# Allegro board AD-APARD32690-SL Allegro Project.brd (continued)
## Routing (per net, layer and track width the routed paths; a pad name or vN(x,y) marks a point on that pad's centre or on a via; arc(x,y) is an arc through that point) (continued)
UNNAMED_3_ADMAX32690_I367_P1_11: length 86.9
  TOP w0.127: U1.A5 v2(98.93,28.05)
  L2_GND w0.102: v2(98.93,28.05) v3(98.32,28.05)
  L3_SIG w0.089: v1(87.12,9.65) 87.12,9.14 88.8,7.46 92.36,7.46 93.66,6.16 132.59,6.16 v1(133.6,7.18) ; v1(86.58,21.88) 89.03,24.32 95.5,24.32 96.96,25.78 96.96,26.7 v3(98.32,28.05)
  L8_SIG w0.089: v1(86.58,21.88) 87.12,21.34 v1(87.12,9.65)
  BOTTOM w0.127: v1(133.6,7.18) 141.99,7.18 142.25,7.44 142.25,8.38 R35.2
UNNAMED_3_ADMAX32690_I367_P1_12: length 53.3
  TOP w0.127: R36.2 v1(128.21,32.77)
  L3_SIG w0.089: v3(100.6,27.7) 99.95,27.05 99.95,25.59 v4(99.63,25.27)
  L4_GND w0.102: v1(97.66,20.13) 97.98,20.45 97.98,23.62 v4(99.63,25.27)
  BOTTOM w0.127: v1(128.21,32.77) 127.44,32 127.44,29.97 122.49,25.02 122.49,19.37 120.21,17.08 98.93,17.08 97.66,18.35 v1(97.66,20.13)
UNNAMED_3_ADMAX32690_I367_P1_15: length 9.3
  L2_GND w0.102: v1(94.09,27.94) 94.55,28.4 v2(99.9,28.4)
  BOTTOM w0.127: v1(94.09,27.94) R38.2
UNNAMED_3_ADMAX32690_I367_P1_16: length 57.3
  TOP w0.102: U1.B1 99.57,26.32
  TOP w0.127: v1(93.3,19.32) 94.03,19.32 96.76,22.05 96.76,23.51 99.57,26.32 ; R37.2 v1(128.21,29.84)
  BOTTOM w0.127: v1(128.21,29.84) 128.21,29.46 127.76,29.02 127.76,26.73 123.25,22.23 123.25,19.11 120.46,16.32 94.55,16.32 93.66,17.21 93.66,18.95 v1(93.3,19.32)
UNNAMED_3_ADMAX32690_I367_P1_19: length 83
  TOP w0.127: R69.2 52.09,47.43 v1(52.83,47.43)
  L3_SIG w0.089: v3(102.7,29.1) 102.84,28.96 103.02,28.96 104.55,27.43 106.84,27.43 106.97,27.3 110.81,27.3 v1(111.2,27.7) ; v1(105.79,43.5) 101.98,43.5 101.47,44.01 63.94,44.01 61.47,46.48 53.78,46.48 v1(52.83,47.43)
  BOTTOM w0.127: v1(105.79,43.5) 105.79,41.08 111.46,35.42 111.46,27.96 v1(111.2,27.7)
UNNAMED_3_ADMAX32690_I367_P1_20: length 20.9
  TOP w0.127: v1(116.2,19.75) 116.8,19.75 R71.2
  L3_SIG w0.089: v3(102.7,28.75) 102.85,28.6 103.02,28.6 104.7,26.92 106.55,26.92 106.71,26.77 113.16,26.77 114.3,25.62 v1(115.32,25.62)
  BOTTOM w0.127: v1(116.2,19.75) 115.32,20.64 v1(115.32,25.62)
UNNAMED_3_ADMAX32690_I367_P1_21: length 66.8
  TOP w0.127: R70.2 61.29,47.38 v1(62.36,47.38)
  L3_SIG w0.089: v1(62.36,47.38) 63.87,47.38 66.48,44.77 103.44,44.77 v1(103.82,44.39)
  L5_PWR w0.102: v1(103.82,44.39) 104.97,43.24 104.97,41.72 105.47,41.21 105.47,32.32 106.74,31.05 106.74,28.07 106.36,27.69 103.92,27.69 103.47,28.13 102.62,28.13 v5(102,28.75)
UNNAMED_3_ADMAX32690_I367_P1_22: length 85.8
  TOP w0.127: U1.M7 103.58,28.75 104.04,29.21 105.12,29.21 105.44,28.89 105.82,28.89 106.08,28.64 108.55,28.64 108.74,28.83 v1(112.52,28.83) ; R72.2 49.55,47.43 v1(50.29,47.43)
  L3_SIG w0.089: v1(50.29,47.43) 51.5,46.23 61.34,46.23 63.94,43.62 101.41,43.62 101.92,43.12 v1(106.81,43.12)
  BOTTOM w0.127: v1(106.81,43.12) 107.19,42.74 107.19,41.28 112.6,35.86 112.6,33.26 113.09,32.77 113.09,29.94 112.52,29.37 v1(112.52,28.83)
UNNAMED_3_ADMAX32690_I367_P1_23: length 55.4
  TOP w0.127: v1(57.91,47.43) 57.17,47.43 R73.2
  L5_PWR w0.102: v1(57.91,47.43) 59.31,47.43 63.82,42.93 83.18,42.93 89.53,36.58 100.01,36.58 101.3,35.29 v5(101.3,29.1)
UNNAMED_3_ADMAX32690_I367_P1_24: length 91.1
  TOP w0.127: v1(45.21,47.43) 44.47,47.43 R44.2
  L2_GND w0.102: v2(103.05,29.1) 104.46,27.69 v3(104.71,27.69)
  L3_SIG w0.089: v1(45.21,47.43) 46.93,45.72 61.09,45.72 63.88,42.93 101.03,42.93 101.6,42.35 v1(106.24,42.35) ; v1(111.82,27.69) 111.44,28.07 111,28.07 110.49,27.56 107.09,27.56 106.97,27.69 v3(104.71,27.69)
  BOTTOM w0.127: v1(111.82,27.69) 111.82,29.75 112.33,30.26 112.33,32.54 111.84,33.04 111.84,35.54 106.24,41.15 v1(106.24,42.35)
UNNAMED_3_ADMAX32690_I367_P1_25: length 75.1
  TOP w0.127: v1(64.51,47.38) 63.83,47.38 R43.2
  L3_SIG w0.089: v1(105.35,44.39) 104.58,45.15 66.74,45.15 v1(64.51,47.38)
  L4_GND w0.102: v1(111.82,25.62) 110.84,26.61 106.68,26.61 106.11,27.18 104.2,27.18 102.63,28.75 v4(102.35,28.75)
  BOTTOM w0.127: v1(105.35,44.39) 105.35,41.02 110.17,36.2 110.17,27.56 111.82,25.91 v1(111.82,25.62)
UNNAMED_3_ADMAX32690_I367_P1_28: length 89.9
  TOP w0.127: v1(47.75,47.43) 47.01,47.43 R45.2
  L2_GND w0.102: v3(104.81,27.18) 104.62,27.18 v2(103.05,28.75)
  L3_SIG w0.089: v3(104.81,27.18) 106.71,27.18 106.84,27.05 111.89,27.05 v1(112.52,27.69) ; v1(106.81,42.35) 106.43,42.74 101.79,42.74 101.28,43.24 63.94,43.24 61.21,45.97 49.21,45.97 v1(47.75,47.43)
  BOTTOM w0.127: v1(106.81,42.35) 106.81,41.08 112.22,35.67 112.22,33.13 112.71,32.64 112.71,30.1 112.14,29.53 112.14,28.07 v1(112.52,27.69)
UNNAMED_3_ADMAX32690_I367_P1_29: length 63.6
  TOP w0.127: R46.2 54.63,47.43 v1(55.37,47.43)
  L3_SIG w0.089: v1(55.37,47.43) 56.07,46.74 61.59,46.74 63.94,44.39 v1(101.65,44.39)
  L5_PWR w0.102: v5(101.65,29.1) v1(101.65,44.39)
UNNAMED_3_ADMAX32690_I367_P1_30: length 8.3
  TOP w0.127: U1.A7 93.52,28.75 v1(92.58,27.81)
  BOTTOM w0.127: R47.2 v1(92.58,27.81)
UNNAMED_3_ADMAX32690_I367_P2: length 37.7
  TOP w0.127: v1(97.6,38.8) 92.14,44.26 77.53,44.26 76.45,45.34 R101.1
  L4_GND w0.102: v4(100.6,28.4) 99.38,29.62 99.38,31.08 98.23,32.23 98.23,37.34 97.6,37.97 v1(97.6,38.8)
UNNAMED_3_ADMAX32690_I367_P2_1: length 45.5
  TOP w0.127: v1(72.12,47.38) 71.49,47.38 R81.1 ; v1(98.42,39.56) 98.11,39.88 98.11,45.28 v1(97.85,45.53)
  L3_SIG w0.089: v1(97.85,45.53) 73.98,45.53 72.13,47.38 v1(72.12,47.38)
  L4_GND w0.102: v4(100.6,28.75) 99.73,29.62 99.73,31.18 98.55,32.35 98.55,37.72 98.04,38.23 98.04,39.18 v1(98.42,39.56)
UNNAMED_3_ADMAX32690_I367_P2_2: length 77.7
  L3_SIG w0.089: v1(95.5,9.43) 95.92,9.02 125.86,9.02 129.86,13.02 v1(133.6,13.02) ; v3(100.6,29.45) 98.81,31.24 v1(95.12,31.24)
  L8_SIG w0.089: v1(95.44,26.48) 96.14,25.78 96.14,10.06 v1(95.5,9.43)
  BOTTOM w0.127: R104.1 141.22,13.46 140.78,13.02 v1(133.6,13.02) ; v1(95.12,31.24) 95.12,29.59 94.96,29.43 94.96,26.96 v1(95.44,26.48)
UNNAMED_3_ADMAX32690_I367_P2_3: length 95.2
  TOP w0.127: R82.1 41.91,47.5 v1(42.74,46.67)
  L2_GND w0.102: v2(100.95,27) 100.95,26.65 v3(99.19,24.89)
  L3_SIG w0.089: v1(42.74,46.67) 43.94,45.47 60.9,45.47 65.34,41.02 66.42,41.02 67.88,39.56 67.88,18.1 71.18,14.8 78.93,14.8 79.98,15.84 83.69,15.84 84.11,15.43 86.55,15.43 87.88,16.76 87.88,17.81 91.98,21.91 96.2,21.91 v3(99.19,24.89)
UNNAMED_3_ADMAX32690_I367_P2_4: length 101.2
  TOP w0.127: v1(42.04,46.67) 37.97,46.67 37.4,46.1 35.81,46.1 35.56,46.36 R103.1
  L3_SIG w0.089: v3(100.95,27.35) 100.95,27.16 100.46,26.67 100.46,25.78 100.58,25.65 100.58,24.89 96.77,21.08 92.46,21.08 88.71,17.34 88.71,16.19 86.8,14.29 79.98,14.29 79.41,13.72 70.48,13.72 66.67,17.53 66.67,39.81 66.1,40.39 61.53,40.39 56.71,45.21 43.5,45.21 v1(42.04,46.67)
UNNAMED_3_ADMAX32690_I367_P2_5: length 52.8
  TOP w0.127: v1(74.68,47.38) 74.03,47.38 R80.1
  L3_SIG w0.089: v1(95.31,45.91) 76.14,45.91 74.68,47.37 v1(74.68,47.38)
  L5_PWR w0.102: v1(94.81,25.08) 95.22,25.5 99.76,25.5 100.71,26.45 100.71,28.16 v5(100.95,28.4)
  BOTTOM w0.127: v1(95.31,45.91) 95.82,45.4 95.82,32.89 96.46,32.26 96.46,26.35 95.19,25.08 v1(94.81,25.08)
UNNAMED_3_ADMAX32690_I367_P2_6: length 47.1
  TOP w0.127: R102.1 79.11,47.38 v1(79.75,47.38)
  L3_SIG w0.089: v1(79.75,47.38) 80.45,46.67 v1(94.93,46.67)
  L5_PWR w0.102: v1(94.81,25.65) 94.96,25.81 99.66,25.81 100.43,26.57 100.43,28.4 100.77,28.75 v5(100.95,28.75)
  BOTTOM w0.127: v1(94.93,46.67) 94.93,45.72 95.5,45.15 95.5,32.7 96.14,32.07 96.14,26.51 95.28,25.65 v1(94.81,25.65)
UNNAMED_3_ADMAX32690_I367_P2_7: length 90.9
  TOP w0.127: R83.1 48.63,6.53 50.41,6.53 52.07,8.19 53.28,8.19 54.17,9.08 54.17,23.18 54.8,23.81 67.12,23.81 68.77,25.46 v1(73.03,25.46)
  L3_SIG w0.089: v1(73.03,25.46) 73.03,38.74 73.98,39.69 95.63,39.69 97.73,37.59 v1(100.39,37.59)
  L4_GND w0.102: v1(100.39,37.59) 100.77,37.21 100.77,29.62 v4(100.95,29.45)
UNNAMED_3_ADMAX32690_I367_P2_8: length 19.9
  TOP w0.127: R105.1 98.87,46.16 98.87,40.45 99.69,39.62 v1(99.69,38.35)
  L4_GND w0.102: v1(99.69,38.35) 100.2,38.35 101.12,37.43 101.12,29.62 v4(101.3,29.45)
UNNAMED_3_ADMAX32690_I367_P2_9: length 25.2
  TOP w0.127: v1(102.17,36.2) 102.17,42.42 102.62,42.86 R106.1
  L3_SIG w0.089: v3(101.65,27.35) v1(101.65,25.08)
  L8_SIG w0.089: v1(102.17,36.2) 101.47,35.5 101.47,25.26 v1(101.65,25.08)
UNNAMED_3_ADMAX32690_I367_P2_10: length 22.6
  TOP w0.127: R84.1 95.11,47.38 95.94,47.38 96.55,46.77 97.57,46.77 98.49,45.85 98.49,40.26 99.25,39.5 v1(99.25,38.8)
  L4_GND w0.102: v4(101.65,29.45) 101.47,29.63 101.47,37.72 100.39,38.8 v1(99.25,38.8)
UNNAMED_3_ADMAX32690_I367_P2_11: length 54.2
  TOP w0.127: R77.1 84.95,47.38 v1(85.59,47.38)
  L3_SIG w0.089: v1(103.82,45.91) 103.06,46.67 98.93,46.67 97.09,48.51 92.65,48.51 92.27,48.13 90.3,48.13 89.98,47.82 87.95,47.82 87.51,47.38 v1(85.59,47.38)
  L4_GND w0.102: v1(109.82,25.02) 109.03,25.81 106.24,25.81 105.63,26.42 103.82,26.42 102.68,27.56 102.49,27.56 v4(102,28.05)
  L8_SIG w0.089: v1(109.82,25.02) 109.66,25.18 109.66,41.97 106.52,45.12 104.62,45.12 v1(103.82,45.91)
UNNAMED_3_ADMAX32690_I367_P2_12: length 37.7
  TOP w0.127: R74.1 126.06,11.3 126.06,12.25 124.9,13.4 116.59,13.4 115.32,14.67 115.32,21.02 114.24,22.1 106.49,22.1 v1(106.17,21.78)
  L5_PWR w0.102: v5(102,28.4) 102.52,27.88 103.31,27.88 104.58,26.61 104.58,25.21 105.73,24.07 105.73,22.99 106.17,22.54 v1(106.17,21.78)
UNNAMED_3_ADMAX32690_I367_P2_13: length 45.7
  TOP w0.127: R98.1 87.49,47.38 v1(88.13,47.38)
  L3_SIG w0.089: v1(102.08,21.91) 102.08,24.16 102.62,24.7 102.62,27.43 v3(102.35,27.7) ; v1(100.96,46.29) 98.81,46.29 96.96,48.13 92.77,48.13 92.46,47.82 90.49,47.82 90.05,47.38 v1(88.13,47.38)
  L8_SIG w0.089: v1(100.96,46.29) 100.96,24.96 102.08,23.84 v1(102.08,21.91)
UNNAMED_3_ADMAX32690_I367_P2_14: length 23.5
  TOP w0.127: R79.1 v1(116.08,28.83)
  L3_SIG w0.089: v3(102.7,28.05) 102.86,27.89 103.05,27.89 104.14,26.8 104.14,25.15 106.01,23.27 115.89,23.27 117.09,24.48 117.09,27.81 v1(116.08,28.83)
UNNAMED_3_ADMAX32690_I367_P2_15: length 19.6
  TOP w0.127: R76.1 106.74,20.1 107.85,21.2 v1(110.93,21.2)
  L4_GND w0.102: v1(110.93,25.02) 110.93,26.03 110.62,26.35 106.49,26.35 105.92,26.92 104.08,26.92 102.6,28.4 v4(102.35,28.4)
  L8_SIG w0.089: v1(110.93,21.2) v1(110.93,25.02)
UNNAMED_3_ADMAX32690_I367_P2_16: length 25.3
  TOP w0.127: R109.1 105.16,6.09 105.09,6.15 105.09,9.4 v1(106.55,10.86)
  L2_GND w0.102: v3(102.87,23.62) 102.87,26.67 102.7,26.84 v2(102.7,27)
  L3_SIG w0.089: v3(102.87,23.62) 102.87,11.49 103.76,10.6 106.3,10.6 v1(106.55,10.86)
UNNAMED_3_ADMAX32690_I367_P2_17: length 30.8
  TOP w0.127: v1(103.93,11.03) 100.65,7.75 93.54,7.75 92.46,6.67 R108.1
  L2_GND w0.102: v2(102.7,27.35) 103.19,26.86 v3(103.19,26.16)
  L3_SIG w0.089: v3(103.19,26.16) 103.19,11.78 v1(103.93,11.03)
UNNAMED_3_ADMAX32690_I367_P2_18: length 26.1
  TOP w0.127: R97.1 v1(107.7,11.24)
  L3_SIG w0.089: v1(107.7,11.24) 106.36,11.24 105.98,10.86 104.65,10.86 103.5,12 103.5,26.29 102.86,26.93 102.86,27.53 v3(102.7,27.7)
UNNAMED_3_ADMAX32690_I367_P2_19: length 16.9
  TOP w0.127: v1(110.36,25.62) 110.36,26.42 110.87,26.92 116.33,26.92 R100.1
  L4_GND w0.102: v4(102.35,28.05) 102.57,28.05 103.95,26.67 105.73,26.67 106.33,26.07 109.92,26.07 v1(110.36,25.62)
UNNAMED_3_ADMAX32690_I367_P2_20: length 18.4
  TOP w0.127: R96.1 109.54,20.1 110.14,20.7 111.35,20.7 v1(111.82,21.18)
  L3_SIG w0.089: v1(111.82,24) 111.35,23.53 106.2,23.53 104.44,25.29 104.44,26.85 103.05,28.24 102.85,28.24 v3(102.7,28.4)
  L8_SIG w0.089: v1(111.82,21.18) v1(111.82,24)
UNNAMED_3_ADMAX32690_I367_P2_21: length 27
  TOP w0.127: U1.L1 103.05,26.21 104.01,25.24 104.01,21.59 v1(105.09,20.51) ; v1(105.28,12.07) 105.28,11.3 100.96,6.99 97.85,6.99 97.54,6.67 R87.1
  L3_SIG w0.089: v1(105.09,20.51) 104.65,20.07 104.65,13.72 105.28,13.08 v1(105.28,12.07)
UNNAMED_3_ADMAX32690_I367_P2_22: length 29.6
  TOP w0.102: 103.38,26.32 103.38,26.67 U1.L2
  TOP w0.127: v1(105.09,21.15) 104.33,21.91 104.33,25.37 103.38,26.32 ; v1(104.84,11.68) 104.84,11.37 100.84,7.37 95.57,7.37 95,6.79 R107.1
  L3_SIG w0.089: v1(105.09,21.15) 104.33,20.38 104.33,12.7 104.84,12.19 v1(104.84,11.68)
UNNAMED_3_ADMAX32690_I367_P2_23: length 24.4
  TOP w0.127: R88.1 102.62,8.13 v1(105.73,11.24)
  L2_GND w0.102: v3(103.63,26.54) 103.63,26.77 v2(103.05,27.35)
  L3_SIG w0.089: v1(105.73,11.24) 104.68,11.24 103.82,12.1 103.82,26.35 v3(103.63,26.54)
UNNAMED_3_ADMAX32690_I367_P2_24: length 39.7
  TOP w0.127: v1(100.97,47.38) 100.19,47.38 R85.1
  L2_GND w0.102: v3(105.6,25.59) 105.16,25.59 v2(103.05,27.7)
  L3_SIG w0.089: v3(105.6,25.59) 108.65,25.59 109.63,24.61 111.41,24.61 v1(111.82,25.02)
  BOTTOM w0.127: v1(100.97,47.38) 100.98,47.37 103.89,47.37 104.9,46.36 104.9,40.89 109.85,35.94 109.85,27.43 111.38,25.91 111.38,25.46 v1(111.82,25.02)
UNNAMED_3_ADMAX32690_I367_P2_25: length 45.7
  TOP w0.127: v1(93.21,47.38) 92.57,47.38 R99.1
  L2_GND w0.102: v3(104.9,26.35) 104.75,26.35 v2(103.05,28.05)
  L3_SIG w0.089: v1(105.35,45.53) 98.55,45.53 96.7,47.38 v1(93.21,47.38) ; v1(110.36,25.02) 109.35,26.04 106.62,26.04 106.23,26.42 105.1,26.42 105.03,26.35 v3(104.9,26.35)
  L8_SIG w0.089: v1(110.36,25.02) 110.33,25.02 110.01,25.34 110.01,42.23 106.71,45.53 v1(105.35,45.53)
UNNAMED_3_ADMAX32690_I367_P2_26: length 23.7
  TOP w0.127: v1(108.58,20.19) 108.27,20.19 108.14,20.07 R75.1
  L2_GND w0.102: v2(103.05,28.4) 104.78,26.67 v3(104.9,26.67)
  L3_SIG w0.089: v1(113.73,25.62) 112.97,26.38 106.68,26.38 106.39,26.67 v3(104.9,26.67)
  L8_SIG w0.089: v1(108.58,20.19) 109.16,19.62 112.78,19.62 113.73,20.57 v1(113.73,25.62)
UNNAMED_3_ADMAX32690_I367_P2_27: length 34
  TOP w0.127: v1(104.39,12.07) 100.46,8.13 90.8,8.13 89.92,7.24 R86.1 ; v1(105.09,21.78) 104.65,22.23 104.65,25.5 103.7,26.45 103.7,26.86 103.56,27 U1.M2
  L3_SIG w0.089: v1(105.09,21.78) 104.08,20.76 104.08,12.38 v1(104.39,12.07)
UNNAMED_3_ADMAX32690_I367_P2_28: length 33.2
  TOP w0.127: v1(104.24,28.42) 103.87,28.05 U1.M5 ; R78.1 90.03,47.38 v1(90.67,47.38)
  L3_SIG w0.089: v1(90.67,47.38) 92.53,47.38 92.96,47.82 96.77,47.82 98.68,45.91 v1(101.66,45.91)
  L8_SIG w0.089: v1(104.24,28.42) 104.46,28.64 104.46,44.32 102.87,45.91 v1(101.66,45.91)
UNNAMED_3_ADMAX32690_I367_P2_29: length 22.5
  TOP w0.127: U1.M6 103.65,28.4 104.2,28.96 104.97,28.96 105.35,28.57 105.66,28.57 105.89,28.35 108.78,28.35 108.9,28.48 113.38,28.48 v1(113.73,28.83) ; v1(110.93,20.19) R95.1
  L8_SIG w0.089: v1(113.73,28.83) 113.22,28.32 113.22,20.76 112.65,20.19 v1(110.93,20.19)
UNNAMED_3_ADMAX32690_I367_P3: length 64.9
  TOP w0.127: R114.1 v1(128.21,34.23)
  L4_GND w0.102: v4(100.6,29.1) 100.08,29.62 100.08,31.27 98.87,32.48 98.87,35.69 99.31,36.13 v1(99.89,36.13)
  BOTTOM w0.127: v1(128.21,34.23) 127.13,33.15 127.13,30.16 122.11,25.15 122.11,19.49 120.71,18.1 104.01,18.1 102.55,19.56 102.55,26.61 100.77,28.38 100.77,35.24 v1(99.89,36.13)
UNNAMED_3_ADMAX32690_I367_P3_1: length 32.7
  TOP w0.127: v1(98.04,15.94) 98.67,16.57 103.06,16.57 R93.1
  L4_GND w0.102: v1(99.89,35.56) 99.89,34.73 100.43,34.19 100.43,29.62 v4(100.95,29.1)
  L8_SIG w0.089: v1(98.04,15.94) 98.04,25.97 98.68,26.61 98.68,33.34 99.89,34.54 v1(99.89,35.56)
UNNAMED_3_ADMAX32690_I367_P3_2: length 78.1
  TOP w0.127: R89.1 69.34,17.4 67.94,18.8 67.94,21.46 69.85,23.37 v1(71.31,23.37)
  L3_SIG w0.089: v3(100.95,29.8) 100.95,30.81 101.41,31.27 101.41,40.26 100.43,41.24 73.25,41.24 71.31,39.31 v1(71.31,23.37)
UNNAMED_3_ADMAX32690_I367_P3_3: length 77.3
  TOP w0.127: R110.1 70.87,16.38 68.26,18.99 68.26,21.21 69.85,22.8 v1(71.75,22.8)
  L2_GND w0.102: v2(100.95,30.15) 100.95,30.53 101.09,30.67 v3(101.09,31.4)
  L3_SIG w0.089: v1(71.75,22.8) 71.75,39.18 73.47,40.89 100.33,40.89 101.09,40.13 v3(101.09,31.4)
UNNAMED_3_ADMAX32690_I367_P3_4: length 75.9
  TOP w0.127: R90.1 72.39,7.75 72.96,8.32 72.96,14.8 68.58,19.18 68.58,20.95 69.91,22.29 v1(72.52,22.29) ; U1.E12 100.95,30.97 100.96,30.99 100.96,39.05 v1(100.39,39.62)
  L3_SIG w0.089: v1(72.52,22.29) 72.52,38.8 73.72,40 100.01,40 v1(100.39,39.62)
UNNAMED_3_ADMAX32690_I367_P3_5: length 79.9
  TOP w0.127: v1(70.87,21.72) 69.91,21.72 68.9,20.7 68.9,19.37 73.34,14.92 73.34,8.32 73.91,7.75 R111.1
  L3_SIG w0.089: v1(70.87,21.72) 70.87,39.43 73.06,41.62 100.49,41.62 101.7,40.42 101.7,31.21 101.3,30.81 v3(101.3,29.8)
UNNAMED_3_ADMAX32690_I367_P3_6: length 77
  TOP w0.127: v1(70.87,18.99) 74.49,15.37 74.49,13.46 81.53,6.41 R92.1 ; U1.F12 101.3,39.29 v1(100.14,40.45)
  L3_SIG w0.089: v1(70.87,18.99) 72.14,20.26 72.14,38.99 73.6,40.45 v1(100.14,40.45)
UNNAMED_3_ADMAX32690_I367_P3_7: length 82.6
  TOP w0.127: R91.1 76.45,7.84 73.72,10.57 73.72,15.05 69.21,19.56 69.21,20.45 69.85,21.08 v1(70.83,21.08)
  L3_SIG w0.089: v3(101.65,29.8) 101.65,30.78 102.01,31.15 102.01,32.39 102.58,32.96 102.58,39.97 100.58,41.97 72.83,41.97 70.42,39.56 70.42,21.49 v1(70.83,21.08)
UNNAMED_3_ADMAX32690_I367_P3_8: length 83.4
  TOP w0.127: v1(69.98,20.51) 69.53,20.07 69.53,19.69 74.1,15.11 74.1,13.21 78.99,8.32 R112.1
  L3_SIG w0.089: v1(69.98,20.51) 69.98,39.69 72.6,42.31 100.69,42.31 102.87,40.13 102.87,32.83 102.3,32.26 102.3,31.02 102,30.72 v3(102,29.8)
UNNAMED_3_ADMAX32690_I367_P3_9: length 88
  TOP w0.127: v1(69.98,19.88) 70.61,19.88 74.87,15.62 74.87,13.72 81.79,6.79 83.76,6.79 84.07,6.48 R113.1
  L3_SIG w0.089: v3(102.35,29.8) 102.35,30.66 103.16,31.46 103.16,40.29 100.81,42.64 72.36,42.64 69.53,39.81 69.53,20.32 v1(69.98,19.88)
UNNAMED_3_ADMAX32690_I367_P4: length 16.3
  TOP w0.127: R94.1 v1(116.17,31.18)
  L3_SIG w0.089: v1(116.17,31.18) 110.78,31.18 v1(109.32,29.72)
  L4_GND w0.102: v1(109.32,29.72) 108.49,28.89 105.22,28.89 105.03,29.08 103.5,29.08 102.93,29.65 102.2,29.65 v4(102,29.45)
UNNAMED_3_ADMAX32690_I367_VREG1: length 5.9
  TOP w0.127: 102.35,32.69 U1.J12
  TOP w0.254: 102.68,33.02 102.35,32.69
  TOP w0.305: 102.68,34.67 102.68,33.02
  TOP w0.381: C18.1 103.42,35.41 102.68,34.67
UNNAMED_3_ANT4PV3_I701_FEED: length 3.8
  TOP w0.152: L5.2 115.32,47.43 C43.2 115.31,49.98 ANT1.4
UNNAMED_3_DIOLED4PV5_I542_C1: length 1.5
  TOP w0.127: R122.2 120.88,3.56 D5.2
UNNAMED_3_DIOLED4PV5_I542_C2: length 1.5
  TOP w0.127: D5.4 119.91,3.56 R118.2
UNNAMED_3_DIOLED_I538_N: length 2.3
  TOP w0.127: DS2.C 125.1,2 R116.2
UNNAMED_3_NC2P_I646_N2: length 1.3
  TOP w0.127: P18.2 63.83,42.76 R127.2
UNNAMED_3_RES_I645_N1: length 1.5
  TOP w0.127: Q4.3 R127.1
UNNAMED_3_RES_I698_N1: length 2.1
  TOP w0.127: Q1.3 126.11,4.2 R116.1
UNNAMED_3_RES_I699_N1: length 1.7
  TOP w0.127: R118.1 Q2.3
UNNAMED_3_RES_I700_N1: length 1.7
  TOP w0.127: R122.1 Q3.3
UNNAMED_7_ADIN1110V2_I781_AVDDH1: length 5.3
  TOP w0.508: v1(58.23,37.91) C64.2 C90.1 58.87,35.83 E6.2
  BOTTOM w0.254: U2.16 58.49,37.65 v1(58.23,37.91) 58.47,38.15 U2.17
UNNAMED_7_ADIN1110V2_I781_AVDDL: length 5
  BOTTOM w0.254: C65.2 59.94,41.66 60.29,41.31 U2.22
  BOTTOM w0.381: E5.2 57.56,42.36 C88.1 C65.2
UNNAMED_7_ADIN1110V2_I781_CEXT2: length 2.2
  BOTTOM w0.254: 58.23,39.15 U2.19
  BOTTOM w0.508: 58.23,39.15 58.13,39.05 C72.2
UNNAMED_7_ADIN1110V2_I781_CEXT3: length 2.1
  BOTTOM w0.254: 58.25,40.32 58.92,39.65 U2.20
  BOTTOM w0.508: C73.1 57.73,40.32 58.25,40.32
UNNAMED_7_ADIN1110V2_I781_DLDO1P1: length 5.7
  BOTTOM w0.254: U2.24 61.29,42.1 C93.2 60.79,42.13 U2.23
  BOTTOM w0.508: C93.2 62.34,42.36 C68.1
UNNAMED_7_ADIN1110V2_I781_LED0: length 3.9
  TOP w0.127: v1(63.29,33.66) 64.26,33.66 64.83,33.08 R139.2
  BOTTOM w0.127: U2.3 v1(63.29,33.66)
UNNAMED_7_ADIN1110V2_I781_LED1: length 5.5
  TOP w0.127: R130.2 63.5,32.58 63.18,32.89 62.23,32.89 61.79,33.33 v1(61.79,33.66) 61.79,34.15 61.53,34.41 R128.2
  BOTTOM w0.127: v1(61.79,33.66) U2.6
UNNAMED_7_ADIN1110V2_I781_TEST1: length 3.1
  BOTTOM w0.127: R125.1 63.7,41.79 63.5,41.59 62.67,41.59 62.29,41.21 U2.26
UNNAMED_7_ADIN1110V2_I781_TX2P4ENN: length 1.5
  TOP w0.127: R137.2 65.31,39.65 v1(65.81,39.65)
  BOTTOM w0.127: U2.31 v1(65.81,39.65)
UNNAMED_7_CAP_I819_N1: length 10.1
  TOP w0.102: v1(42.88,32.82) 42.88,33.1 43.03,33.25 43.03,33.89 42.7,34.22 41.84,34.22 41.64,34.02 T1.7 40.21,34.02 40.01,34.22 39.62,34.22 38.87,33.46 C102.1 R150.1
  BOTTOM w0.102: v1(42.88,32.82) 42.88,33.26 42.33,33.81 R151.2
UNNAMED_7_CAP_I819_N2: length 17.9
  TOP w0.102: R150.2 C102.2 35.04,33.15 34.94,33.25 34.94,34.12 34.84,34.23 33.97,34.23 33.85,34.1 33.85,33.37 P54.1 32.38,33.37 32.38,34.12 32.28,34.23 29.79,34.23 29.69,34.12 L6.3 28.07,33.08 27.41,32.42 R154.1
UNNAMED_7_CAP_I823_N1: length 10.6
  TOP w0.102: R149.1 38.87,37.85 C101.1 38.87,35.23 39.62,34.47 40,34.47 40.19,34.67 T1.6 41.63,34.67 41.82,34.47 42.81,34.47 43.28,34 43.28,33.24 43.43,33.08 v1(43.43,32.82)
  BOTTOM w0.102: R148.2 44,33.81 43.43,33.24 v1(43.43,32.82)
UNNAMED_7_CAP_I823_N2: length 18
  TOP w0.102: R153.1 27.41,36.16 27.94,35.62 L6.4 29.69,34.58 29.79,34.48 32.28,34.48 32.38,34.58 32.38,35.34 P53.1 33.85,35.34 33.85,34.61 33.97,34.48 34.84,34.48 34.94,34.58 34.94,35.46 35.04,35.56 C101.2 35.87,37.85 R149.2
UNNAMED_7_CAP_I855_N1: length 4.8
  BOTTOM w0.254: R152.2 41.06,30.8 38.77,30.8 38.49,31.08 C105.1
UNNAMED_7_CAP_I861_N1: length 17.5
  TOP w0.381: T1.5 41.12,36.67 41.31,36.86 41.31,38.77 41.75,39.21 47.13,39.21 C97.1 v1(47.15,40.07) ; C99.2 v1(47.15,32.7)
  BOTTOM w0.381: v1(47.15,40.07) 47.15,36.39 C94.1 47.15,36.38 v1(47.15,32.7)
UNNAMED_7_CHOKE4PV5_I912_N1: length 8.7
  TOP w0.102: R153.2 24.41,36.16 23.88,35.62 L6.1 22.19,34.7 21.97,34.48 20.77,34.48 20.66,34.58 20.66,34.95 20.56,35.05 R155.1
UNNAMED_7_CHOKE4PV5_I912_N2: length 8.6
  TOP w0.102: R156.1 20.56,33.66 20.66,33.76 20.66,34.12 20.77,34.23 21.97,34.23 22.19,34 L6.2 23.75,33.08 24.41,32.42 R154.2
UNNAMED_7_DIOLED_I752_N: length 1.6
  TOP w0.127: R139.1 DS3.C
UNNAMED_7_DIOLED_I761_N: length 1.6
  TOP w0.127: R130.1 DS4.C
UNNAMED_7_RES_I857_N1: length 4.5
  TOP w0.203: v6(44.48,31.05) 44.48,33.82 44.68,34.02 T1.3
  BOTTOM w0.203: R152.1 v6(44.48,31.05)
UNNAMED_7_RES_I906_N2: length 1.7
  TOP w0.127: S4.3A R166.2
UNNAMED_7_RES_I907_N2: length 1.7
  TOP w0.127: R167.2 S4.2A
UNNAMED_7_RES_I909_N2: length 1.7
  TOP w0.127: 114.68,10.1 R138.2
UNNAMED_9_ADMAXQ1065_I325_CEXT: length 1.4
  TOP w0.127: U8.1 108.07,16.44 108.14,16.51
  TOP w0.457: C91.1 109.47,16.51 108.14,16.51
UNNAMED_9_ADMAXQ1065_I325_PDWN: length 3
  TOP w0.127: 105.54,13.72 105.4,13.58 ; 105.4,13.58 105.56,13.42 ; 105.4,13.58 U8.7 ; 105.4,13.58 104.38,13.58 R165.1 104.28,13.59 P23.1
UNNAMED_9_CAP_I264_N1: length 7.8
  TOP w0.508: P13.6 145.26,38.64 C111.1 143.04,38.62 C109.2 140.15,38.62 140.14,38.61 JP3.2
  TOP w0.762: P13.6 P13.12
UNNAMED_9_CAP_I265_N1: length 8.5
  TOP w0.508: P8.6 144.07,2.03 144.03,2 C114.1 142.13,2 C113.2 141.53,1.98 140.72,2.79 JP4.2
  TOP w0.762: P8.12 P8.6
UNNAMED_9_CN12PV3_I138_P1: length 8
  TOP w0.127: JP9.2 P8.1
UNNAMED_9_CN12PV3_I138_P2: length 5.6
  TOP w0.127: JP7.2 P8.2
UNNAMED_9_CN12PV3_I138_P3: length 8
  TOP w0.127: JP8.2 P8.3
UNNAMED_9_CN12PV3_I138_P4: length 5.6
  TOP w0.127: JP10.2 P8.4
UNNAMED_9_CN12PV3_I138_P8: length 11.6
  TOP w0.127: JP5.2 145.03,17.27 146.56,15.75 146.56,13.46 P8.8
UNNAMED_9_CN12PV3_I138_P9: length 13.7
  TOP w0.127: P8.9 146.56,8.38 146.56,6.54 145.92,5.91 144.08,5.91 142.75,4.57 JP6.2
UNNAMED_9_CN16PAB4GND_I308_N3: length 6.8
  TOP w0.508: P10.B5 5.4,25.98 4.83,25.4 4.83,20.33 R158.2
UNNAMED_9_CN16PAB4GND_I314_N3: length 2.5
  TOP w0.508: R157.2 10.09,28.53 P10.A5
USB_DN: length 111.5
  TOP w0.102: U1.C12 100.25,31.13 99.79,31.59 99.41,31.59 98.99,32.01 98.99,32.05 98.98,32.06
  TOP w0.152: v1(48.45,26.16) 48.16,25.86 47.96,25.86 47.82,26 47.82,26.26 47.66,26.41 47.43,26.41 47.26,26.24 47.26,25.15 47.45,24.96 66.1,24.96 70.74,29.59 70.74,39.37 73.28,41.91 91.5,41.91 98.55,34.86 98.55,32.48 98.98,32.06
  BOTTOM w0.152: L7.1 13.38,26.84 13.63,27.09 14.58,27.09 15.39,26.28 47.9,26.28 48.03,26.16 v1(48.45,26.16)
USB_DN_CM: length 5.5
  TOP w0.152: P10.A7 7.12,26.83 P10.B7
  BOTTOM w0.152: L7.2 10.72,26.84 10.47,27.09 10.01,27.09 9.68,26.76 D6.C 9.4,26.76 9.06,27.1 8.42,27.1 8.15,26.83 P10.A7
USB_DP: length 111.6
  TOP w0.102: 98.76,31.84 98.77,31.83 98.81,31.83 99.3,31.34 99.68,31.34 99.99,31.03 99.99,30.6 U1.B12
  TOP w0.152: 98.76,31.84 98.25,32.36 98.25,34.74 91.38,41.61 73.41,41.61 71.04,39.24 71.04,29.46 66.23,24.65 47.33,24.65 46.96,25.02 46.96,26.37 47.3,26.71 v1(48.45,26.71)
  BOTTOM w0.152: L7.4 13.38,27.64 13.63,27.39 14.71,27.39 15.51,26.59 47.9,26.59 48.03,26.71 v1(48.45,26.71)
USB_DP_CM: length 5.5
  BOTTOM w0.152: L7.3 10.72,27.64 10.47,27.39 10.01,27.39 9.68,27.72 D7.C 9.37,27.72 9.05,27.4 8.42,27.4 8.15,27.68 P10.A6 7.12,27.68 P10.B6
VPWR_IN: length 5.6
  TOP w1.016: F3.1 4.84,9.89 P14.2
VPWR_USB: length 34.3
  TOP w0.254: U4.7 46.31,17.59 46.06,17.84 v6(46.04,17.84) 45.81,17.62 U4.8
  TOP w0.406: P10.B9 P10.A4
  TOP w0.508: P10.B4 P10.A9 10.73,25.13 D10.C
  L5_PWR w0.508: P10.B9 5.44,29.38 5.02,28.96 5.02,25.53 5.42,25.13 P10.B4
  BOTTOM w0.508: D3.A 11.68,15.11 10.73,16.07 10.73,24.61 10.22,25.12 C120.1 9.52,25.13 P10.A9
  vias: v6(45.4,18.48) v6(45.4,17.84)
VREF_ADC: length 84.6
  TOP w0.152: 101.85,33.66 101.65,33.45 U1.G12
  TOP w0.381: v1(102.17,33.97) 101.85,33.66
  L5_PWR w0.508: P5.3 39.37,49.66 39.94,49.09 101.47,49.09 102.93,47.62 102.93,34.46 102.45,33.97 v1(102.17,33.97)
  BOTTOM w0.381: v1(102.17,33.97) C22.1
VUSB0P9: length 4.3
  L2_GND w0.127: v1(99.38,32.77) 100.08,32.77 100.77,32.07 100.77,30.8 100.6,30.62 v2(100.6,30.15)
  BOTTOM w0.381: C35.1 99.38,33.35 v1(99.38,32.77)
XTAL_I: length 5.6
  BOTTOM w0.127: Y1.1 61.66,29.33 61.03,29.96 C62.1 60.79,32.06 U2.8
XTAL_O: length 4.2
  BOTTOM w0.127: U2.9 60.29,32.04 C63.1 60.13,31.74 60.13,30.65 Y1.3

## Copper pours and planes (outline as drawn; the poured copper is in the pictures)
1V8_D on TOP: 40.39,10.1 40.32,10.03 40.32,8.13 40.39,8.06 42.16,8.06 42.23,8.13 42.23,10.03 42.16,10.1
1V8_D on TOP: 101.41,12.53 100.39,12.53 99.76,13.17 97.54,13.17 97.47,13.23 97.47,13.74 97.54,13.8 101.54,13.8 101.6,13.74 101.6,12.73
1V8_D on L6_PWR: 74.87,39.18 74.87,21.97 74.99,21.84 85.28,21.84 91.06,27.62 98.62,27.62 100.77,25.46 100.77,19.3 99.89,18.41 99.89,12.57 100.08,12.38 102.68,12.38 102.93,12.64 102.93,24.7 104.11,25.88 106.2,25.88 108.46,23.62 127.06,23.62 127.57,24.13 127.57,30.04 127,30.61 106.81,30.61 105.16,32.26 95.38,32.26 88.26,39.37 75.06,39.37
GND on TOP, BOTTOM, L3_SIG, L4_GND, L5_PWR, L7_GND, L8_SIG, L9_GND: 116.27,52.83 151.89,52.83 151.89,0.51 0.51,0.51 0.51,34.29 12.83,34.29 19.18,27.94 36.2,27.94 38.23,29.97 38.23,43.43 36.45,45.21 30.86,45.21 28.83,47.24 28.83,52.83 112.08,52.83 112.08,49.02 116.27,49.02
GND on L2_GND: 116.27,52.83 151.89,52.83 151.89,0.51 0.51,0.51 0.51,34.29 12.83,34.29 19.18,27.94 36.2,27.94 38.23,29.97 38.23,43.43 36.45,45.21 30.86,45.21 28.83,47.24 28.83,52.83 112.08,52.83 112.08,49.09 116.27,49.09
GND_EARTH on BOTTOM, L2_GND, L3_SIG, L4_GND, L5_PWR, L6_PWR, L7_GND, L8_SIG, L9_GND: 0.51,52.83 26.29,52.83 26.29,45.97 29.59,42.67 35.56,42.67 35.69,42.55 35.69,30.35 35.43,30.1 20.32,30.1 13.59,36.83 0.51,36.83
VDD_1P1_D on TOP: 30.35,4.32 30.23,4.19 30.23,3.18 30.35,3.05 33.4,3.05 33.53,3.18 33.53,4.32
VDD_1P1_D on BOTTOM: 28.77,5.33 28.77,4.38 30.23,2.92 32.45,2.92 32.64,3.11 32.64,4.32 31.69,4.32 31.69,5.21 31.5,5.4 28.83,5.4
VDD_3P3_D on TOP: 109.41,13.08 108.2,13.08 107.95,13.34 107.95,13.72 108.08,13.84 111.12,13.84 111.25,13.72 111.25,12.45 111.12,12.32 110.17,12.32
VDD_3P3_D on TOP: 40.51,18.73 40.58,18.67 42.55,18.67 42.55,20.95 42.29,21.21 40.77,21.21 40.51,20.95
VDD_3P3_D on TOP: 146.49,23.11 146.49,16.95 146.69,16.76 148.21,16.76 148.4,16.95 148.4,23.11
VDD_3P3_D on BOTTOM: 40.77,21.08 40.64,20.95 40.64,19.88 41.91,19.88 41.91,20.95 41.78,21.08
VDD_3P3_D on L3_SIG, L8_SIG: 40.77,21.08 40.64,20.95 40.64,20.07 40.77,19.94 41.78,19.94 41.91,20.07 41.91,20.95 41.78,21.08
VDD_3P3_D on L6_PWR: 116.59,52.07 151.13,52.07 151.13,1.27 1.27,1.27 1.27,33.53 12.51,33.53 18.86,27.18 36.51,27.18 38.99,29.66 38.99,43.75 36.76,45.97 31.18,45.97 29.59,47.56 29.59,52.07 111.76,52.07 111.76,48.74 116.59,48.74
VDD_5P0 on TOP: 52.7,12.64 48.64,12.64 48.64,11.24 49.15,10.73 49.85,10.73 50.16,10.41 50.16,9.78 50.29,9.65 52.83,9.65 52.96,9.78 52.96,12.38
VDD_5P0 on TOP: 56.45,12.38 56.32,12.26 56.32,7.94 56.45,7.81 57.72,7.81 57.85,7.94 57.85,10.73 58.67,11.56 58.67,12.38
VDD_5P0 on TOP: 52.64,6.92 52.58,6.86 52.58,4.64 53.28,3.94 53.28,2.35 53.98,2.35 53.98,6.86 53.91,6.92
VDD_5P0 on BOTTOM, L3_SIG, L8_SIG: 50.74,10.79 50.61,10.67 50.61,9.78 50.74,9.65 52.26,9.65 52.39,9.78 52.39,10.67 52.26,10.79
VDD_5P0 on BOTTOM, L8_SIG: 56.45,8.95 56.32,8.83 56.32,7.94 56.45,7.81 57.34,7.81 57.47,7.94 57.47,8.83 57.34,8.95
VDD_5P0 on L3_SIG: 56.45,8.95 56.32,8.83 56.32,7.81 56.45,7.68 58.42,7.68 58.42,8.13 57.59,8.95
VDD_5P0 on L5_PWR: 49.28,8.06 28.89,8.06 26.54,10.41 26.54,17.34 47.28,17.34 47.94,16.67 49.97,16.67 49.97,14.48 52.13,12.32 58.67,12.32 59.5,11.49 59.5,7.05 56.9,7.05 54.55,4.7 54.55,1.65 54.29,1.4 52.9,1.4 52.64,1.65 52.64,4.7
VDD_5P0_INT on TOP: 48.99,20.38 48.77,20.16 48.77,18.67 48.16,18.07 48.16,16.22 49.31,16.22 49.66,16.57 49.66,20.38
VDD_5P0_INT on TOP: 27.69,20.32 27.69,22.67 30.29,22.67 30.99,23.37 30.99,24.51 31.12,24.64 34.16,24.64 34.29,24.51 34.29,20.57 33.85,20.13 27.88,20.13
VDD_5P0_INT on BOTTOM, L3_SIG, L8_SIG: 31.94,24.32 31.81,24.19 31.81,22.67 31.94,22.54 33.46,22.54 33.59,22.67 33.59,24.19 33.46,24.32
VDD_5P0_INT on L5_PWR: 47.43,17.91 48.16,17.18 49.97,17.18 49.97,19.88 48.13,21.72 36.07,21.72 33.46,24.32 20.64,24.32 19.37,23.05 19.37,10.41 22.54,10.41 22.73,10.6 22.73,16.26 24.38,17.91
IO_REF_ARD on TOP: 45.02,6.92 44.96,6.86 44.96,4.64 45.66,3.94 45.66,2.35 46.36,2.35 46.36,6.86 46.29,6.92
LT8692S_1P8 on TOP: 25.21,8.95 25.15,8.89 25.15,6.99 25.21,6.92 26.86,6.92 26.92,6.99 26.92,8.95
LT8692S_1P8 on TOP: 33.53,10.54 33.15,10.92 33.15,11.94 37.21,11.94 38.1,12.83 38.1,13.78 42.55,13.78 42.55,10.67 42.42,10.54
LT8692S_1P8 on BOTTOM: 40.26,11.94 40.26,13.72 40.51,13.97 42.16,13.97 42.16,12.19 41.91,11.94
LT8692S_1P8 on L3_SIG: 40.39,13.91 40.39,12.13 40.51,12 42.04,12 42.16,12.13 42.16,13.91
LT8692S_1P8 on L8_SIG: 40.39,12.07 40.39,13.97 42.16,13.97 42.16,12.07 42.04,11.94 40.51,11.94
LT8692S_3P3 on TOP: 20.26,8.95 20.19,8.89 20.19,6.99 20.26,6.92 21.91,6.92 21.97,6.99 21.97,8.95
LT8692S_3P3 on TOP: 33.53,18.16 33.15,17.78 33.15,16.76 37.21,16.76 38.1,15.88 38.1,14.86 42.55,14.86 42.55,18.16
LT8692S_3P3 on BOTTOM: 40.26,14.99 40.26,16.76 42.16,16.76 42.16,14.73 40.51,14.73
LT8692S_3P3 on L3_SIG: 40.51,16.7 40.39,16.57 40.39,14.8 42.16,14.8 42.16,16.57 42.04,16.7
LT8692S_3P3 on L8_SIG: 40.39,14.73 40.39,16.64 40.51,16.76 42.04,16.76 42.16,16.64 42.16,14.73
UNNAMED_2_ADLT3040_I358_OUT1 on TOP: 56.45,16.45 56.32,16.57 56.32,20.57 56.9,20.57 57.4,20.07 57.4,18.03 58.04,17.4 58.04,16.45
UNNAMED_2_ADLT8692S_I193_EN on TOP (solid shape): 27.3,15.24 28.19,15.24 28.26,15.2 28.26,14.54 28.13,14.48 26.99,14.48 26.86,14.35 25.34,14.35 24.45,13.46 8.57,13.46 8.51,13.53 8.51,15.75 26.8,15.75
UNNAMED_2_ADLT8692S_I193_SW1 on TOP (solid shape): 31.43,17.97 30.35,16.89 30.35,15.75 30.26,15.56 30.1,15.56 30.1,16.89 29.02,17.97 28,17.97 27.69,18.29 27.69,19.43 31.43,19.43
UNNAMED_2_ADLT8692S_I193_SW2 on TOP (solid shape): 37.21,15.49 37.21,14.54 37.15,14.48 30.86,14.48 30.61,14.61 30.61,14.72 32,14.72 33.08,15.8 36.91,15.8
UNNAMED_2_ADLT8692S_I193_SW3 on TOP (solid shape): 37.21,14.16 37.21,13.21 36.89,12.89 33.08,12.89 32,13.97 30.61,13.97 30.61,14.1 30.86,14.22 37.15,14.22
VPWR_IN on L5_PWR: 3.62,10.92 3.62,9.21 4.13,8.7 16.76,8.7 18.54,10.48 18.54,23.43 20.19,25.08 33.85,25.08 36.45,22.48 48.45,22.48 50.67,20.26 50.67,14.86 52.51,13.02 59.05,13.02 60.33,11.75 60.33,2.16 60.77,1.71 61.85,1.71 62.29,2.16 62.29,17.72 55.44,24.57 39.24,24.57 36.89,26.92 18.48,26.92 15.81,24.26 15.81,13.34 13.91,11.43 4.13,11.43
VPWR_USB on TOP: 44.96,17.05 44.96,18.64 45.09,18.76 45.5,18.76 46.42,17.84 46.42,16.22 45.78,16.22
VPWR_USB on BOTTOM: 46.36,17.49 46.55,17.68 46.55,18.73 46.36,18.92 11.68,18.92 11.3,19.3 11.3,24.42 10.32,25.4 6.25,25.4 6.25,24.86 10.1,24.86 10.51,24.45 10.51,15.91 11.62,14.8 18.29,14.8 18.32,14.83 18.32,16.45 19.37,17.49

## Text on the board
Ref Des/Assembly Bottom: A | C
Ref Des/Silkscreen Bottom: A | C | SECONDARY SIDE | 08-073637 REV A Z
User.Comments: 5.    SMOOTHEN EDGES AND FREE FROM BURRS AFTER DEPANELIZATION PROCESS. | 4.    RoHS COMPLIANCE: ASSEMBLY VENDOR SHOULD ASSURE COMPLIANCE | 6.    BOARDS TO BE SHIPPED SINGULATED AFTER ASSEMBLY PROCESS. | WITH LEAD-FREE AND RoHS PCB ASSEMBLY STANDARDS (EU RoHS | DIRECTIVE 2002/95/EC). | 7.    ADD SOLDER BLOB ON PINS 2 & 3 FOR THE FOLLOWING LOCATIONS. | 8.    TRIM EXCESS PINS FOR THE FOLLOWING LOCATIONS. | -JP1 | -JP2 | -JP3 | -JP4 | -JP5 | -JP6 | -P2 | -P3 | -P5 | -P6 | -JP7 | -JP8 | -JP9 | -JP10 | -JP11 | FOR Y1 & Y2 | FOR L6
Ref Des/Assembly Top: 1 | 2 | 3 | MATE_ENTRY
Ref Des/Silkscreen Top: C | A | EVAL-MAX32690-ARDZ | PRIMARY SIDE | 08-073637 REV A Z
PAGE_OUTLINE: A1 | ECR-114576 | 23MAY23 | M. BANCISOR | CUSTOMER EVALUATION Z
BODY_CENTER: FAB NOTES REVISION: 2ND NOVEMBER 2022 | 8.   IMPEDANCE REQUIREMENTS: IF NO STACKUP IS DEFINED, THE VENDOR IS ALLOWED TO ADJUST THE DIELECTRIC | 13.  PLATING SPECIFICATION: | 9.   FILLET OPTIONS TO ENHANCE RELIABILITY AT PAD JUNCTIONS WHERE SPACING PERMITS. | 10.  THIEVING: | 11.  LAYER TO LAYER REGISTRATION SHALL BE WITHIN 0.003 INCHES. | 12.  DRILL SIZES ARE FINISHED HOLE SIZES. ALL HOLES SHALL BE LOCATED WITHIN 0.005 INCHES DTP,UNLESS SPECIFIED. | 14.  SURFACE FINISH: | 15.  SOLDERMASK: | 1.   DIMENSIONS ARE IN INCHES (EXCEPT WHERE NOTED). | ALL DOCUMENTS & SPECIFICATIONS REFERRED TO BELOW SHOULD BE THE LATEST REVISIONS. | 2.  BOARD MATERIAL:(USE CHECKED ITEMS) | 3.   ALL LAMINATES & BONDING MATERIALS SHOULD BE SELECTED FROM IPC-4101 OR IPC-4103,(TG>170 DEGC TD>300 DEGC) | 4.   REFER TO IPC-6010 SERIES, CLASS 2 FOR FABRICATION. | 5.   REFER TO LAMINATION DIAGRAM FOR OVERALL BOARD THICKNESS, TOLERANCE APPLIES AFTER ALL LAMINATION AND PLATING | 6.   BOW & TWIST NOT TO EXCEED 0.0075 INCHES (0.75%) PER LINEAR INCH AND SHOULD BE MEASURED PER IPC-TM-650, METHOD 2.4.22. | 7.   ACCEPTABILITY PER ADI SPECIFICATION TST00115. | 16.  APPLY SILKSCREEN TO BOTH SIDES USING A NON-CONDUCTIVE, EPOXY BASED INK PER ARTWORK. | ( ) FILLETS ALLOWED | (X) FILLETS NOT ALLOWED | ( ) VENDOR MAY ADD THIEVING TO COMPENSATE FOR LOW COPPER DENSITY AREAS MAINTAINING A MINIMUM | ( ) VENDOR MAY NOT ADD THIEVING TO COMPENSATE FOR LOW COPPER DENSITY AREAS. | (X) LPI | ( ) OTHER_________ | COLOR | (X) GREEN | (X) WHITE | ( ) OTHER | HINDER PROPER SOLDER WICKING. BARREL RELIEF ON SOLDERMASK ALLOWED IN UNFILLED VIA IN PAD HOLES. | (X) REFER TO LAMINATION DIAGRAM FOR FINISHED COPPER WEIGHT/THICKNESS REQUIRMENTS | (X) IMMERSION GOLD (ENIG) 1.58-3.94 MICRO INCHES OVER 118-236 MICRO INCHES MIN. OF ELECTROLESS NICKEL PER IPC-4552 | THICKNESS & TRACE WIDTHS TO MEET THE IMPEDANCE REQUIREMENT. IF SPECIFIED, THE VENDOR MUST | TRACE WIDTH & SPACING THAT IMPACT THE REQUIREMENTS MUST HAVE WRITTEN APPROVAL FROM ADI. | MINIMUM BARREL PLATING OF 0.001 INCHES. PLATED HOLES SHALL NOT BE ROUGH OR IRREGULAR SO AS TO | SOLDERMASK OVER BARE COPPER OR BARE GOLD (BOTH SIDES) TO MEET IPC-SM-840. | IF PRESENT,DO NOT MODIFY SOLDERMASK DEFINED PADS (MASK OPENINGS LESS THAN COPPER PAD) WITHOUT APPROVAL. | MEET THE REQUIREMENTS LISTED IN THE IMPEDANCE TABLE. ANY ADJUSTMENT MADE TO THE DEFINED STACKUP, | ( ) OSP (ORGANIC SOLDERABILITY PRESERVATIVE) | ( ) IMMERSION SILVER | ( ) SOFT WIRE BONDABLE GOLD 30-50 MICRO INCHES OF SOFT WIRE | ( ) EDGE CONNECTOR FINGERS ARE TO BE PLATED WITH 100 MICRO-INCHES(.0001") OF LOW STRESS | ( ) OTHER: _____________ | PROCESSES. FINISHED THICKNESS MEASURED FROM TOP COPPER TO BOTTOM COPPER. | (X)  ISOLA 370HR OR S1000-2 OR IT180 OR EQUIVALENT | ( )  ISOLA-FR408HR OR EQUIVALENT | ( )  ISOLA IS410 | ( )  MEGTRON 6 | ( )  NELCO-4000-13 | ( )  ROGERS 4350B | ( ) ROGERS 3003 | ( ) ARLON 85N | ( ) EM370D | ( )  OTHER ________________________ | X | UL FLAMMABILITY RATING 94V-0. BOARD MATERIAL & CONSTRUCTION SHALL MEET THE REQUIREMENTS OF UL796/UL796F. | BONDABLE GOLD OVER 100-150 MICRO INCHES OF NICKEL | NICKEL UNDER 30 MICRO-INCHES (.0003') OF GOLD | FOR MAX32690GWE+ (U1) AREA: | 0.100 INCH CLEARANCE FROM ALL COPPER FEATURES, | THE STARTING COPPER WEIGHT/THICKNESS CAN VARY AS LONG AS THE FINISHED COPPER | WEIGHT/THICKNESS IS NOT LESS THAN THE SPECIFIED VALUE. | UNLESS OTHERWISE SPECIFIED | THICKNESS OF GOLD IS LIMITED TO 1.2 MICRO INCHES TO 2.5 MICRO INCHES TO PREVENT EMBRITTLEMENT. | HOMOGENOUS MATERIALS IN THIS BOARD SHALL BE COMPLAINT WITH THE EU DIRECTIVE 2002/95/EC | WORKMANSHIP SHALL CONFORM TO IPC-A-600, CLASS 2. | 21.  INTENTIONAL SHORTS: | 17.  FINAL ELECTRICAL TEST TO BE PERFORMED USING PROVIDED IPC-D-356A NETLIST OR ODB++ FORMAT FILE. | 22.  PEMNUTS: | 23.  MANUFACTURER TO ETCH/STAMP WITH PERMANENT NON-CONDUCTIVE INK | ON SECONDARY SIDE UNLESS OTHERWISE SPECIFIED: | 18.  A TIME DOMAIN REFLECTOMETER REPORT (TDR) FOR EACH IMPEDANCE CONTROLLED LAYER & A CERTIFICATE | 19.  IF PRESENT, ALL BLIND/BURIED VIAS WITH AN ASPECT RATIO <1:1 TO BE PLATED SHUT WITH COPPER WHEN | 20.  FOR VIA FILL INFORMATION REFER TO DRILL CHART: | 25. PANELIZATION: | 27.  MINIMUM DESIGN LINE WIDTH IS .003 INCH. | 28.  MINIMUM DESIGN LINE SPACING IS .004 INCH. | IS ACCEPTABLE, ALL OTHER INSTANCES MUST BE REPORTED. | IF AN INTENTIONAL SHORT REPORT IS SUPPLIED AND DOES NOT MATCH THE FAB DATA THEN | THE PCB SHALL HAVE A VERIFICATION STAMP. | ( )  NON-CONDUCTIVE EPOXY FILL ALL 0.XXXX INCHES DRILLED VIAS | ( )  COPPER FILL ALL 0.XXXX INCHES DRILLED VIAS | ( ) PEMNUTS TO BE INSTALLED BY FABRICATOR | ( ) PEMNUTS NOT TO BE INSTALLED BY FABRICATOR | ( ) NOT APPLICABLE | USED AS VIA-IN-PAD OR AS A STACKED VIA. BLIND/BURIED VIAS WITH AN ASPECT RATIO >1:1 TO BE FILLED | A. UL CODE-FLAMMABILITY RATING FOR THOSE APPROVED MATERIALS(IF APPLICABLE) | B. DATE CODE | C. LOT NUMBER | D. MANUFACTURER LOGO | BOARDS TO BE SHIPPED IN ARRAY AND KEPT INTACT | PANEL TO BE SUBJECTED TO CUSTOMERS APPROVAL | PANEL SOLDER PASTE STENCIL GERBER TO BE PROVIDED TO ANALOG | CAN'T BE PERFORMED BECAUSE THE TRACE LENGTH IS TOO SHORT ON THE OUTER LAYERS AT THE PIN ESCAPES | ADI APPROVAL IS REQUIRED. | OF COMPLIANCE SHALL BE PROVIDED BY VENDOR AT TIME OF SHIPMENT. INSTANCES WHERE TDR TESTING | WITH NON-CONDUCTIVE EPOXY. | (THICKNESS AFTER PLATING) | 0.5 OZ, 0.0007" | 0.0032 | 0.0035 | 0.0276 | FINAL CU | CU CLAD | L3 | L8 | 0.00350 SE / NA | - | REFERENCE | L2/L4 | L7/L9 | L2 | L9 | LAYER | NUMBER | THE FINISHED PCB THICKNESS TO BE: | 1 | 2 | 3 | 4 | 5 | 6 | 7 | 8 | 9 | 10 | TOP | L2_GND | L3_SIG | L4_GND | L5_PWR | L6_PWR | L7_GND | L8_SIG | L9_GND | BOTTOM | NAME | COPPER THICKNESS | (OZ,INCH) | LAMINATION DIAGRAM | 0.062" +/-10% | DIELECTRIC | THICKNESS (INCH) | ISOLA 370HR/EQUIVALENT | MATERIALS | TOOLING: | FINISH: | NOTES: | MATERIAL: | TESTING: | MISCELLANEOUS: | 10-LAYER STACKUP
DIMENSION: (REF) | DIA MAX
User.11: C | A
User.15: NOTE: IMPEDANCE TOLERANCE +/-10% | SE = SINGLE ENDED,  DP = DIFFERENTIAL PAIR | 2
User.17: L2 GND | 08-      -07
User.18: L3 SIG | 08-      -08
User.19: L4 GND | 08-      -09
User.20: L5 PWR | 08-      -10
User.24: L6 PWR | 08-      -11
User.25: L7 GND | 08-      -12
User.26: DIA MAX / SEE NOTE 19 | 3 | BVIA_1-2
User.27: DIA MAX / SEE NOTE 19 | 4 | BVIA_2-3
User.28: DIA MAX / SEE NOTE 19 | 5 | BVIA_3-4
User.29: L8 SIG | 08-      -13
User.30: L9 GND | 08-      -14
User.32: DIA MAX / SEE NOTE 19 | 6 | BVIA_4-5
User.34: FILMMASK PRIMARY | 08-      -17
User.45: FIGURE | SIZE | 8.0 | 10.0 | 16.0 | 30.0 | 40.0 | 43.0 | 45.0 | 55.0 | 71.0 | 63.0x28.0 | 79.0x28.0 | 4.0 | PLATED | DRILL CHART: TOP to BOTTOM | ALL UNITS ARE IN MILS | DRILL CHART: L4_GND to L5_PWR | DRILL CHART: L2_GND to L3_SIG | DRILL CHART: L3_SIG to L4_GND | DRILL CHART: TOP to L2_GND | QTY | 477 | 551 | 16 | 14 | 24 | 9 | 61 | 5 | 1 | 2 | 12 | 33 | 547 | 88 | TOLERANCE/NOTES
